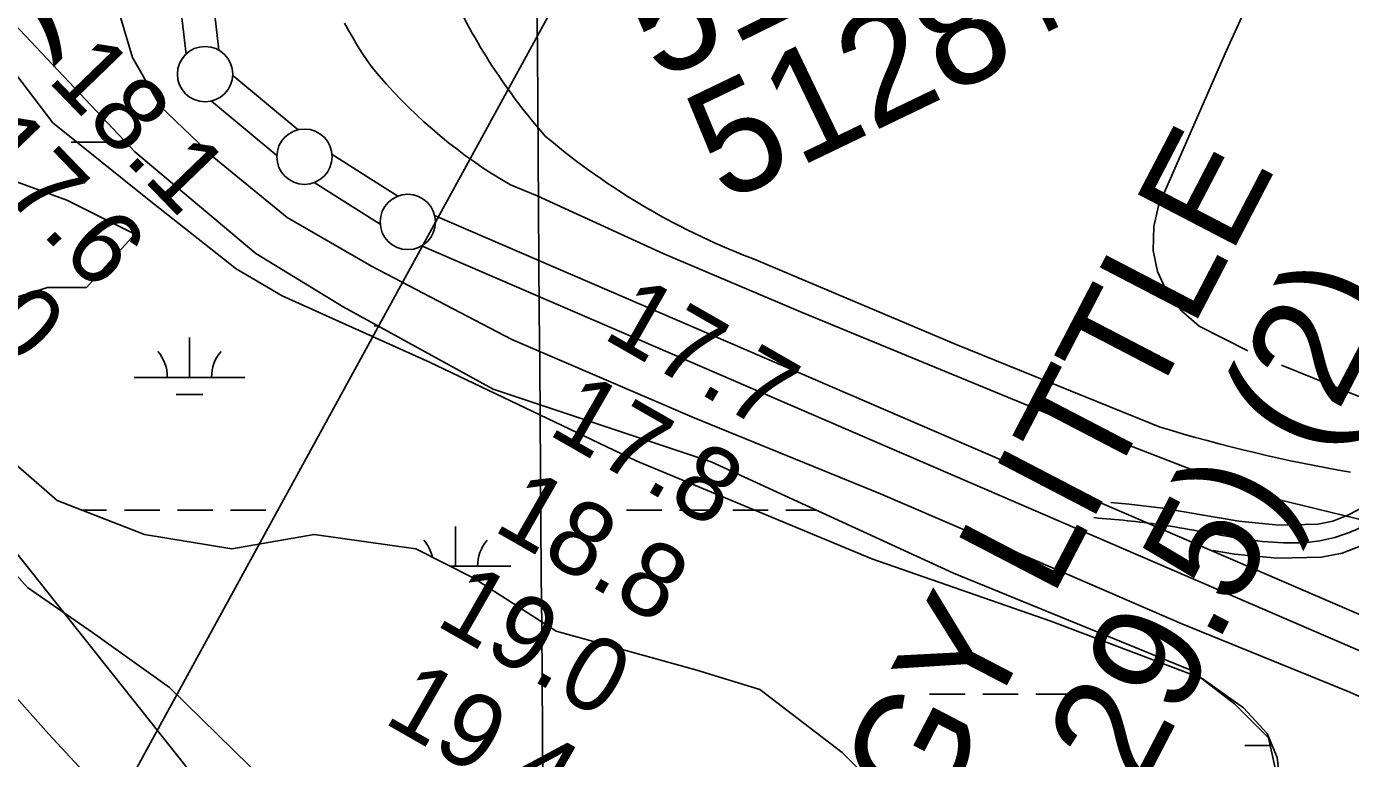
# Model space of a CAD drawing. Extents: x 3535183 to 3573198, y 534952 to 560562.
# Drawn here: x 3554681 to 3555878, y 547926 to 548588 of the extents above; entities that cross this region are included whole.
import ezdxf

# ---------------------------------------------------------------- set-up
doc = ezdxf.new("R2010")
doc.units = 0
for name, color, linetype in [('V-CHAN-NAID', 7, 'Continuous'), ('V-GRID-MAJR', 7, 'Continuous'), ('V-LEVE-TOET', 7, 'Continuous'), ('V-RIVR-RANG', 7, 'Continuous'), ('V-ROAD-CNTR', 7, 'Continuous'), ('V-SITE-VEGE', 7, 'Continuous'), ('V-SURV-IDEN', 7, 'Continuous'), ('V-SURV-LINE', 7, 'Continuous'), ('V-TOPO-DPTH', 7, 'Continuous'), ('V-TOPO-MINR', 7, 'Continuous'), ('V-TOPO-SHOR', 7, 'Continuous'), ('V-UTIL-LINE', 7, 'Continuous'), ('V-WETL-SWMP', 7, 'Continuous')]:
    doc.layers.add(name, color=color, linetype=linetype)

msp = doc.modelspace()

# ---------------------------------------------------------------- linework, layer by layer
at = {"layer": 'V-GRID-MAJR'}
msp.add_spline([(3555204.1780000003, 540472.404), (3555158.363, 546529.794), (3555112.522, 552590.651), (3555066.681, 558651.524), (3555066.6550000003, 558654.975)], degree=3, dxfattribs=at)
at = {"layer": 'V-LEVE-TOET'}
for points in [[(3554872.819, 549672.087), (3554853.13, 549510.196), (3554837.0300000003, 549286.297), (3554808.149, 548992.953), (3554774.5640000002, 548715.986), (3554767.642, 548638.75), (3554766.137, 548596.233), (3554777.1040000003, 548559.584), (3554802.511, 548515.542), (3554850.545, 548469.1900000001), (3554916.919, 548415.059), (3554993.0300000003, 548371.08), (3555119.875, 548304.936), (3555284.559, 548234.155), (3555453.14, 548165.332), (3555612.751, 548096.4990000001), (3555725.534, 548047.885), (3555877.336, 547986.062), (3555936.2630000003, 547959.6140000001), (3555996.9620000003, 547934.307)], [(3554968.735, 548590.835), (3554972.4620000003, 548583.888), (3554976.366, 548577.039), (3554980.443, 548570.2930000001), (3554984.691, 548563.654), (3554989.111, 548557.125), (3554993.694, 548550.71), (3554999.924, 548543.2660000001), (3555006.312, 548535.954), (3555012.855, 548528.78), (3555019.548, 548521.747), (3555026.39, 548514.858), (3555033.376, 548508.116), (3555040.505, 548501.5210000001), (3555047.773, 548495.082), (3555055.1750000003, 548488.797), (3555062.71, 548482.672), (3555070.3710000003, 548476.71), (3555078.16, 548470.91), (3555086.0670000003, 548465.278), (3555094.093, 548459.816), (3555102.234, 548454.524), (3555110.483, 548449.408), (3555118.839, 548444.468), (3555142.835, 548434.697)], [(3557110.29, 547599.3960000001), (3556987.346, 547660.1460000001), (3556959.6410000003, 547668.3150000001), (3556918.279, 547676.079), (3556890.961, 547686.198), (3556867.546, 547694.761), (3556824.61, 547720.082), (3556810.557, 547730.212), (3556800.696, 547737.484), (3556756.977, 547765.534), (3556579.002, 547853.936), (3556402.2060000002, 547929.073), (3556326.795, 547957.9), (3556167.941, 548039.296), (3556002.078, 548107.032), (3555923.642, 548131.54), (3555907.745, 548136.928), (3555905.349, 548137.5160000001), (3555790.292, 548165.694), (3555611.944, 548234.587), (3555382.466, 548329.184), (3555257.19, 548382.131), (3555142.835, 548434.697)]]:
    msp.add_lwpolyline(points, dxfattribs=at)
at = {"layer": 'V-ROAD-CNTR'}
for points in [[(3555705.875549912, 548225.600522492), (3555521.50191866, 548300.3853729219), (3555342.440276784, 548375.9952217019)], [(3555918.172125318, 548182.9056078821), (3555911.4181388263, 548173.8816259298), (3555904.41115284, 548166.057641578), (3555895.0301716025, 548157.6856583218), (3555884.252193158, 548150.563672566), (3555875.507210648, 548145.9056818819), (3555862.0112376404, 548140.57169255), (3555848.425264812, 548137.9236978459), (3555812.9853356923, 548137.098699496), (3555777.024407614, 548140.4676927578), (3555743.183475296, 548146.490680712), (3555708.308545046, 548152.275669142), (3555677.7566061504, 548155.9156618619), (3555661.1506393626, 548157.4516587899)], [(3555942.190077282, 548164.927643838), (3555934.64609237, 548154.8496639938), (3555925.639110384, 548144.79168411), (3555913.382134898, 548133.855705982), (3555899.608162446, 548124.753724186), (3555888.1131854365, 548118.629736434), (3555870.4652207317, 548111.653750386), (3555851.665258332, 548107.99175771), (3555811.9313378, 548107.0667595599), (3555772.990415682, 548110.7137522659), (3555753.7584541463, 548114.1377454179)]]:
    msp.add_lwpolyline(points, dxfattribs=at)
for centre, radius, start, end in [((3555571.103829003, 548856.3947813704), 559.016158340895, 204.82545644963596, 221.16386200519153), ((3555569.9276699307, 548985.2390199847), 650.3295470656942, 229.81061935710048, 249.5247026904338), ((3556117.9965751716, 549582.8089581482), 1418.3999708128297, 253.1089007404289, 260.2554007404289)]:
    msp.add_arc(centre, radius, start, end, dxfattribs=at)
msp.add_spline([(3555930.1811013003, 548173.91662586), (3555915.025131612, 548155.4246628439), (3555891.930177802, 548137.6586983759), (3555850.045261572, 548122.957727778), (3555775.007411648, 548125.590722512), (3555706.1925492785, 548137.4216988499), (3555646.0596695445, 548143.783686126)], degree=3, dxfattribs=at)
at = {"layer": 'V-SITE-VEGE'}
for points in [[(3554620.718, 548611.296), (3554705.106, 548500.545), (3554790.629, 548431.941), (3554870.683, 548368.7930000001), (3554912.46, 548344.245), (3555045.582, 548284.268), (3555232.194, 548195.067), (3555445.339, 548106.675), (3555606.9450000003, 548050.234), (3555743.964, 547998.455), (3555781.06, 547971.95), (3555802.543, 547948.557), (3555811.538, 547927.102), (3555814.684, 547901.351)], [(3554897.239, 547905.22), (3554810.5330000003, 547990.214), (3554741.026, 548040.101), (3554682.066, 548080.633), (3554651.207, 548114.9450000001)]]:
    msp.add_lwpolyline(points, dxfattribs=at)
at = {"layer": 'V-SURV-LINE'}
for points in [[(3554825.441834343, 548562.736257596), (3554817.9499781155, 548626.27025103)], [(3554847.7411064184, 548629.8042447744), (3554855.2329588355, 548566.2702836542)], [(3554867.624884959, 548543.4284750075), (3554926.709895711, 548494.3369093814)], [(3554907.5408932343, 548471.2598784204), (3554848.454766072, 548520.3523716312)], [(3554957.399847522, 548472.0408795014), (3555016.98683886, 548434.4037998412)], [(3555000.959888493, 548409.0436556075), (3554941.3720941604, 548446.6812424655)], [(3555050.155944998, 548416.9094078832), (3556065.726109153, 547978.7496932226)], [(3556053.859713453, 547951.196308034), (3555038.2890289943, 548389.356247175)]]:
    msp.add_lwpolyline(points, dxfattribs=at)
for centre in [(3554842.67841, 548544.6544000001), (3554932.48742, 548470.0351400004), (3555025.87228, 548411.0502200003)]:
    msp.add_circle(centre, 25, dxfattribs=at)
at = {"layer": 'V-TOPO-DPTH'}
msp.add_lwpolyline([(3554743.506341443, 547902.7044229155), (3554701.371593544, 547948.1993946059), (3554660.092826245, 547994.4376874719)], dxfattribs=at)
at = {"layer": 'V-TOPO-MINR'}
for points in [[(3555884.8000882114, 547248.4180927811), (3555857.5484923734, 547259.4077188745), (3555852.3937537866, 547261.5632938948), (3555847.2782445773, 547263.8053578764), (3555842.2215794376, 547266.1771552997), (3555837.204143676, 547268.6354416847), (3555832.2351113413, 547271.1940068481), (3555827.291316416, 547273.799635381), (3555822.385377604, 547276.4758589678), (3555817.5046762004, 547279.1991459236), (3555031.459117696, 547725.2072463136), (3555021.9292537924, 547730.9663507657), (3555012.6316348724, 547737.0594708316), (3555003.6823834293, 547743.6536143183), (3554994.965376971, 547750.5817734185), (3554917.6686313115, 547815.5605924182), (3554896.364639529, 547834.8676382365), (3554876.1012888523, 547855.1402893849), (3554543.150390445, 548273.6418179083)], [(3554743.506341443, 547902.7044229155), (3554701.371593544, 547948.1993946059), (3554660.092826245, 547994.4376874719)]]:
    msp.add_lwpolyline(points, dxfattribs=at)
at = {"layer": 'V-TOPO-SHOR'}
msp.add_line((3555941.715, 548230.698), (3555815.657, 548281.6950000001), dxfattribs=at)
msp.add_lwpolyline([(3555785.213, 548294.542), (3555741.107, 548316.741), (3555725.1, 548330.7710000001), (3555710.648, 548350.655), (3555703.611, 548366.255), (3555699.693, 548385.3690000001), (3555700.0640000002, 548406.826), (3555704.34, 548425.557), (3555765.856, 548566.06), (3555837.112, 548722.959), (3555927.054, 548926.692), (3556025.949, 549151.888)], dxfattribs=at)
at = {"layer": 'V-UTIL-LINE'}
msp.add_line((3553438.224, 545464.3910000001), (3555206.2970000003, 548695.002), dxfattribs=at)
at = {"layer": 'V-WETL-SWMP'}
for p, q in [((3554721.690674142, 548483.2203181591), (3554753.690674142, 548483.2203181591)), ((3554769.690674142, 548483.2203181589), (3554770.962575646, 548483.2203181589)), ((3554995.598674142, 548317.0463181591), (3554999.137247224, 548317.0463181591)), ((3554828.534674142, 548270.6163181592), (3554828.534674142, 548306.6163181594)), ((3554778.5346741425, 548270.6163181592), (3554878.534674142, 548270.6163181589)), ((3554816.534674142, 548255.1853181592), (3554840.534674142, 548255.1853181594)), ((3554731.5809570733, 548150.5453181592), (3554753.690674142, 548150.5453181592)), ((3554769.690674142, 548150.5453181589), (3554801.690674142, 548150.5453181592)), ((3554817.690674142, 548150.5453181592), (3554849.690674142, 548150.5453181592)), ((3554865.690674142, 548150.5453181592), (3554897.690674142, 548150.5453181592)), ((3555223.598674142, 548150.5453181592), (3555255.598674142, 548150.5453181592)), ((3555271.598674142, 548150.5453181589), (3555303.598674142, 548150.5453181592)), ((3555319.598674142, 548150.5453181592), (3555351.598674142, 548150.5453181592)), ((3555367.598674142, 548150.5453181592), (3555395.3631513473, 548150.5453181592)), ((3555069.006674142, 548099.8033181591), (3555069.006674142, 548135.8033181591)), ((3555064.5117660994, 548099.8033181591), (3555119.0066741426, 548099.8033181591)), ((3555497.506674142, 547984.3713181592), (3555529.5066741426, 547984.3713181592)), ((3555545.506674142, 547984.3713181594), (3555577.506674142, 547984.3713181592)), ((3555593.506674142, 547984.3713181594), (3555625.506674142, 547984.3713181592)), ((3555782.3506741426, 547937.9413181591), (3555805.255316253, 547937.9413181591))]:
    msp.add_line(p, q, dxfattribs=at)
for points in [[(3554630.282, 548632.177), (3554779.154, 548474.547), (3554888.619, 548382.5970000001), (3554967.434, 548334.432), (3555103.17, 548259.996), (3555300.207, 548194.317), (3555519.136, 548093.61), (3555733.687, 548006.0380000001), (3555773.095, 547975.388), (3555803.745, 547944.738), (3555812.502, 547905.33)], [(3554630.282, 548330.054), (3554700.34, 548351.947), (3554735.3680000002, 548351.947), (3554779.154, 548400.111), (3554717.8540000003, 548430.761), (3554669.69, 548448.276)], [(3555449.079, 547900.952), (3555418.429, 547931.602), (3555343.9930000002, 547988.524), (3555287.071, 548006.0380000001), (3555160.092, 548041.067), (3555085.656, 548089.231), (3555033.113, 548115.503), (3554941.162, 548128.639), (3554866.7260000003, 548115.503), (3554787.912, 548128.639), (3554709.097, 548159.289), (3554643.418, 548216.21)]]:
    msp.add_lwpolyline(points, dxfattribs=at)
for centre, radius, start, end in [((3554773.291738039, 548271.0911213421), 35.24628790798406, 359.2281799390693, 40.771838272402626), ((3554883.777610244, 548271.0911213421), 35.24628790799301, 139.2281769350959, 180.77183526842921), ((3555013.76373804, 548100.2781213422), 35.24628790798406, 12.62232957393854, 40.77183827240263), ((3555124.2496102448, 548100.2781213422), 35.24628790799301, 139.2281769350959, 180.77183526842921)]:
    msp.add_arc(centre, radius, start, end, dxfattribs=at)

# ---------------------------------------------------------------- texts
at = {"layer": 'V-CHAN-NAID'}
for s, height, rotation, p in [('ENTERGY INTAKE -DISCHARGE (129.8)', 100.00000200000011, 44.40730259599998, (3552926.8040215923, 546850.5628246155)), ('ENTERGY LITTLE ', 100.00000200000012, 62.49444963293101, (3555292.3767542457, 547463.9991674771)), (' GYPSY (129.5) (2)', 100.00000200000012, 62.49444963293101, (3555385.8858137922, 547315.6276051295))]:
    msp.add_text(s, height=height, rotation=rotation, dxfattribs=at).set_placement(p)
at = {"layer": 'V-RIVR-RANG'}
for s, height, rotation, p in [('18.1', 67, 314.0283257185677, (3554699.2448998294, 548539.1655511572)), ('17.6', 67, 314.0283257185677, (3554624.5816127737, 548472.5240551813)), ('17.0', 67, 314.0283257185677, (3554552.1172910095, 548403.6066811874)), ('17.7', 66.99999999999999, 330.17832571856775, (3555200.588257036, 548306.8363189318)), ('17.8', 66.99999999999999, 330.17832571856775, (3555151.0672570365, 548219.9593189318)), ('18.8', 66.99999999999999, 330.17832571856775, (3555101.5462570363, 548133.0813189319)), ('19.0', 66.99999999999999, 330.17832571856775, (3555049.507916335, 548047.6472784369)), ('19.4', 66.99999999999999, 330.17832571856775, (3555002.5042570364, 547959.3273189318))]:
    msp.add_text(s, height=height, rotation=rotation, dxfattribs=at).set_placement(p)
at = {"layer": 'V-SURV-IDEN'}
for s, height, rotation, p in [('5127+77.1', 100, 26.166696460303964, (3555252.4796575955, 548537.5212149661)), ('5128+87.5', 100.00000000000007, 25.723802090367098, (3555311.925386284, 548427.6762086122))]:
    msp.add_text(s, height=height, rotation=rotation, dxfattribs=at).set_placement(p)

doc.saveas('drawing.dxf')
